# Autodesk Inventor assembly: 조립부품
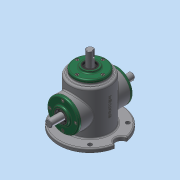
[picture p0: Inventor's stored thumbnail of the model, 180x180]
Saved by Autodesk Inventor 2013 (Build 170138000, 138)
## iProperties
Created: 2018-04
Part Number: 조립부품
Document SubType Name: Assembly
Designer: dgall
Author: dgall
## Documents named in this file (16)
- C:\Users\dgall\Desktop\480407V1020\조립부품.iam
- C:\Users\dgall\Desktop\480407V1020\본체.ipt
- C:\Users\dgall\Desktop\480407V1020\메인 베벨기어.ipt
- C:\Users\dgall\Desktop\480407V1020\메인 축.ipt
- 메인 축.ipt
- C:\Users\dgall\Desktop\480407V1020\베어링 6203.ipt
- C:\Users\dgall\Desktop\480407V1020\볼트 M4.ipt
- 볼트 M4.ipt
- C:\Users\dgall\Desktop\480407V1020\서브 베벨기어.ipt
- C:\Users\dgall\Desktop\480407V1020\서브 축.ipt
- 서브 축.ipt
- C:\Users\dgall\Desktop\480407V1020\오일 실.ipt
- 오일 실.ipt
- C:\Users\dgall\Desktop\480407V1020\커버.ipt
- C:\Users\dgall\Desktop\480407V1020\키 4x4.ipt
- C:\Users\dgall\Desktop\480407V1020\키 5x5.ipt
